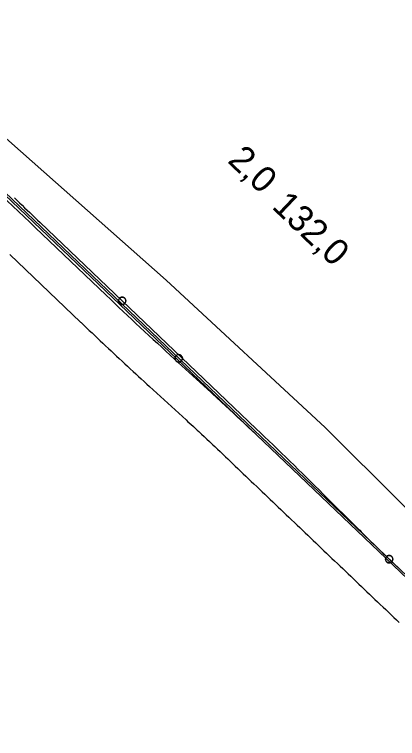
# Model space of a CAD drawing. Extents: x -670810 to -649614, y -1131928 to -1115069.
# Drawn here: x -666009 to -664978, y -1126558 to -1124610 of the extents above; entities that cross this region are included whole.
import ezdxf

# ---------------------------------------------------------------- set-up
doc = ezdxf.new("R2010")
doc.units = 0
for name, color, linetype in [('hranice_VRT_ZUR_Vysocina', 7, 'Continuous'), ('Situace - Osa koleje 2D', 7, 'Continuous'), ('Staničení - hlavní staničení + kolečka 1k', 7, 'Continuous')]:
    doc.layers.add(name, color=color, linetype=linetype)

# ---------------------------------------------------------------- blocks, each defined once
blk = doc.blocks.new('Sit10Kruh_109')
at = {"layer": 'Staničení - hlavní staničení + kolečka 1k'}
blk.add_lwpolyline([(10, 0), (9.98026, 0.6279), (9.92114, 1.25334), (9.82288, 1.87382), (9.68584, 2.4869), (9.51056, 3.09016), (9.29776, 3.68124), (9.04828, 4.2578), (8.76306, 4.81754), (8.44328, 5.35826), (8.09016, 5.87786), (7.70514, 6.37424), (7.28968, 6.84548), (6.84548, 7.28968), (6.37424, 7.70514), (5.87786, 8.09016), (5.35826, 8.44328), (4.81754, 8.76306), (4.2578, 9.04828), (3.68124, 9.29776), (3.09016, 9.51056), (2.4869, 9.68584), (1.87382, 9.82288), (1.25334, 9.92114), (0.6279, 9.98026), (0, 10), (-0.6279, 9.98026), (-1.25334, 9.92114), (-1.87382, 9.82288), (-2.4869, 9.68584), (-3.09016, 9.51056), (-3.68124, 9.29776), (-4.2578, 9.04828), (-4.81754, 8.76306), (-5.35826, 8.44328), (-5.87786, 8.09016), (-6.37424, 7.70514), (-6.84548, 7.28968), (-7.28968, 6.84548), (-7.70514, 6.37424), (-8.09016, 5.87786), (-8.44328, 5.35826), (-8.76306, 4.81754), (-9.04828, 4.2578), (-9.29776, 3.68124), (-9.51056, 3.09016), (-9.68584, 2.4869), (-9.82288, 1.87382), (-9.92114, 1.25334), (-9.98026, 0.6279), (-10, 0), (-9.98026, -0.6279), (-9.92114, -1.25334), (-9.82288, -1.87382), (-9.68584, -2.4869), (-9.51056, -3.09016), (-9.29776, -3.68124), (-9.04828, -4.2578), (-8.76306, -4.81754), (-8.44328, -5.35826), (-8.09016, -5.87786), (-7.70514, -6.37424), (-7.28968, -6.84548), (-6.84548, -7.28968), (-6.37424, -7.70514), (-5.87786, -8.09016), (-5.35826, -8.44328), (-4.81754, -8.76306), (-4.2578, -9.04828), (-3.68124, -9.29776), (-3.09016, -9.51056), (-2.4869, -9.68584), (-1.87382, -9.82288), (-1.25334, -9.92114), (-0.6279, -9.98026), (0, -10), (0.6279, -9.98026), (1.25334, -9.92114), (1.87382, -9.82288), (2.4869, -9.68584), (3.09016, -9.51056), (3.68124, -9.29776), (4.2578, -9.04828), (4.81754, -8.76306), (5.35826, -8.44328), (5.87786, -8.09016), (6.37424, -7.70514), (6.84548, -7.28968), (7.28968, -6.84548), (7.70514, -6.37424), (8.09016, -5.87786), (8.44328, -5.35826), (8.76306, -4.81754), (9.04828, -4.2578), (9.29776, -3.68124), (9.51056, -3.09016), (9.68584, -2.4869), (9.82288, -1.87382), (9.92114, -1.25334)], close=True, dxfattribs=at)
blk.add_circle((0, 0), 10, dxfattribs=at)
blk = doc.blocks.new('Sit10Kruh_185')
at = {"layer": 'Staničení - hlavní staničení + kolečka 1k'}
blk.add_lwpolyline([(10, 0), (10, 0.6), (9.9, 1.3), (9.8, 1.9), (9.7, 2.5), (9.5, 3.1), (9.3, 3.7), (9, 4.3), (8.8, 4.8), (8.4, 5.4), (8.1, 5.9), (7.7, 6.4), (7.3, 6.8), (6.8, 7.3), (6.4, 7.7), (5.9, 8.1), (5.4, 8.4), (4.8, 8.8), (4.3, 9), (3.7, 9.3), (3.1, 9.5), (2.5, 9.7), (1.9, 9.8), (1.3, 9.9), (0.6, 10), (0, 10), (-0.6, 10), (-1.3, 9.9), (-1.9, 9.8), (-2.5, 9.7), (-3.1, 9.5), (-3.7, 9.3), (-4.3, 9), (-4.8, 8.8), (-5.4, 8.4), (-5.9, 8.1), (-6.4, 7.7), (-6.8, 7.3), (-7.3, 6.8), (-7.7, 6.4), (-8.1, 5.9), (-8.4, 5.4), (-8.8, 4.8), (-9, 4.3), (-9.3, 3.7), (-9.5, 3.1), (-9.7, 2.5), (-9.8, 1.9), (-9.9, 1.3), (-10, 0.6), (-10, 0), (-10, -0.6), (-9.9, -1.3), (-9.8, -1.9), (-9.7, -2.5), (-9.5, -3.1), (-9.3, -3.7), (-9, -4.3), (-8.8, -4.8), (-8.4, -5.4), (-8.1, -5.9), (-7.7, -6.4), (-7.3, -6.8), (-6.8, -7.3), (-6.4, -7.7), (-5.9, -8.1), (-5.4, -8.4), (-4.8, -8.8), (-4.3, -9), (-3.7, -9.3), (-3.1, -9.5), (-2.5, -9.7), (-1.9, -9.8), (-1.3, -9.9), (-0.6, -10), (0, -10), (0.6, -10), (1.3, -9.9), (1.9, -9.8), (2.5, -9.7), (3.1, -9.5), (3.7, -9.3), (4.3, -9), (4.8, -8.8), (5.4, -8.4), (5.9, -8.1), (6.4, -7.7), (6.8, -7.3), (7.3, -6.8), (7.7, -6.4), (8.1, -5.9), (8.4, -5.4), (8.8, -4.8), (9, -4.3), (9.3, -3.7), (9.5, -3.1), (9.7, -2.5), (9.8, -1.9), (9.9, -1.3)], close=True, dxfattribs=at)
blk.add_circle((0, 0), 10, dxfattribs=at)
blk = doc.blocks.new('Sit10Kruh_186')
at = {"layer": 'Staničení - hlavní staničení + kolečka 1k'}
blk.add_lwpolyline([(10, 0), (10, 0.6), (9.9, 1.3), (9.8, 1.9), (9.7, 2.5), (9.5, 3.1), (9.3, 3.7), (9, 4.3), (8.8, 4.8), (8.4, 5.4), (8.1, 5.9), (7.7, 6.4), (7.3, 6.8), (6.8, 7.3), (6.4, 7.7), (5.9, 8.1), (5.4, 8.4), (4.8, 8.8), (4.3, 9), (3.7, 9.3), (3.1, 9.5), (2.5, 9.7), (1.9, 9.8), (1.3, 9.9), (0.6, 10), (0, 10), (-0.6, 10), (-1.3, 9.9), (-1.9, 9.8), (-2.5, 9.7), (-3.1, 9.5), (-3.7, 9.3), (-4.3, 9), (-4.8, 8.8), (-5.4, 8.4), (-5.9, 8.1), (-6.4, 7.7), (-6.8, 7.3), (-7.3, 6.8), (-7.7, 6.4), (-8.1, 5.9), (-8.4, 5.4), (-8.8, 4.8), (-9, 4.3), (-9.3, 3.7), (-9.5, 3.1), (-9.7, 2.5), (-9.8, 1.9), (-9.9, 1.3), (-10, 0.6), (-10, 0), (-10, -0.6), (-9.9, -1.3), (-9.8, -1.9), (-9.7, -2.5), (-9.5, -3.1), (-9.3, -3.7), (-9, -4.3), (-8.8, -4.8), (-8.4, -5.4), (-8.1, -5.9), (-7.7, -6.4), (-7.3, -6.8), (-6.8, -7.3), (-6.4, -7.7), (-5.9, -8.1), (-5.4, -8.4), (-4.8, -8.8), (-4.3, -9), (-3.7, -9.3), (-3.1, -9.5), (-2.5, -9.7), (-1.9, -9.8), (-1.3, -9.9), (-0.6, -10), (0, -10), (0.6, -10), (1.3, -9.9), (1.9, -9.8), (2.5, -9.7), (3.1, -9.5), (3.7, -9.3), (4.3, -9), (4.8, -8.8), (5.4, -8.4), (5.9, -8.1), (6.4, -7.7), (6.8, -7.3), (7.3, -6.8), (7.7, -6.4), (8.1, -5.9), (8.4, -5.4), (8.8, -4.8), (9, -4.3), (9.3, -3.7), (9.5, -3.1), (9.7, -2.5), (9.8, -1.9), (9.9, -1.3)], close=True, dxfattribs=at)
blk.add_circle((0, 0), 10, dxfattribs=at)

msp = doc.modelspace()

# ---------------------------------------------------------------- linework, layer by layer
at = {"layer": 'hranice_VRT_ZUR_Vysocina'}
for points in [[(-665993.2, -1124977.6), (-666490.4, -1124537.4), (-666642.8, -1124402.4)], [(-665993.2, -1124977.6), (-665600.9, -1125324.5), (-665173.4, -1125720.6), (-664760.4, -1126131.5), (-664347, -1126557.9)], [(-666022.4, -1125255.4), (-665831.4, -1125437.6), (-665829.9, -1125438.9), (-665822.6, -1125445.9), (-665815.3, -1125452.8), (-665808, -1125459.8), (-665800.7, -1125466.7), (-665793.4, -1125473.6), (-665786, -1125480.6), (-665778.7, -1125487.5), (-665771.4, -1125494.4), (-665764, -1125501.3), (-665756.7, -1125508.2), (-665749.3, -1125515.1), (-665741.9, -1125522), (-665734.6, -1125528.9), (-665727.2, -1125535.7), (-665719.8, -1125542.6), (-665712.4, -1125549.5), (-665705, -1125556.3), (-665697.6, -1125563.2), (-665690.2, -1125570), (-665682.8, -1125576.9), (-665675.4, -1125583.7), (-665668, -1125590.5), (-665660.6, -1125597.3), (-665653.1, -1125604.1), (-665645.8, -1125610.8), (-665547.5, -1125700.7), (-665542.4, -1125705.4), (-665535.1, -1125712), (-665527.9, -1125718.7), (-665520.6, -1125725.4), (-665517.2, -1125728.6), (-665513.4, -1125732.1), (-665506.2, -1125738.8), (-665499, -1125745.5), (-665491.8, -1125752.2), (-665484.6, -1125758.9), (-665477.4, -1125765.7), (-665475.4, -1125767.5), (-665470.2, -1125772.4), (-665463.1, -1125779.2), (-665455.9, -1125786), (-665448.7, -1125792.8), (-665441.6, -1125799.6), (-665435.2, -1125805.6)], [(-665435.2, -1125805.6), (-665429.7, -1125810.9), (-665422.5, -1125817.8), (-665415.2, -1125824.7), (-665408, -1125831.6), (-665400.8, -1125838.5), (-665393.5, -1125845.4), (-665386.3, -1125852.3), (-665379.1, -1125859.2), (-665371.8, -1125866.1), (-665364.6, -1125873), (-665357.3, -1125879.9), (-665350.1, -1125886.8), (-665342.9, -1125893.7), (-665335.6, -1125900.6), (-665328.4, -1125907.5), (-665321.2, -1125914.4), (-665313.9, -1125921.3), (-665306.7, -1125928.2), (-665299.5, -1125935.1), (-665292.2, -1125942), (-665285, -1125948.9), (-665277.7, -1125955.8), (-665270.5, -1125962.7), (-665263.3, -1125969.6), (-665256, -1125976.5), (-665248.8, -1125983.5), (-665241.6, -1125990.4), (-665234.3, -1125997.3), (-665227.1, -1126004.2), (-665219.8, -1126011.1), (-665212.6, -1126018), (-665205.4, -1126024.9), (-665198.1, -1126031.8), (-665190.9, -1126038.7), (-665183.7, -1126045.6), (-665176.4, -1126052.5), (-665169.2, -1126059.4), (-665162, -1126066.3), (-665154.7, -1126073.2), (-665147.5, -1126080.1), (-665140.2, -1126087), (-665133, -1126093.9), (-665125.8, -1126100.8), (-665118.5, -1126107.7), (-665111.3, -1126114.6), (-665104.1, -1126121.5), (-665096.8, -1126128.4), (-665089.6, -1126135.3), (-665082.3, -1126142.2), (-665075.1, -1126149.1), (-665067.9, -1126156), (-665060.6, -1126162.9), (-665053.4, -1126169.8), (-665046.2, -1126176.7), (-665038.9, -1126183.6), (-665031.7, -1126190.5), (-665024.5, -1126197.4), (-665017.2, -1126204.3), (-665010, -1126211.2), (-665002.7, -1126218.1), (-664995.5, -1126225), (-664988.3, -1126231.9), (-664981, -1126238.8), (-664973.8, -1126245.7)]]:
    msp.add_lwpolyline(points, dxfattribs=at)
at = {"layer": 'Situace - Osa koleje 2D'}
for p, q in [((-667875.9, -1123340), (-664682.6, -1126385.2)), ((-667872.7, -1123336.5), (-664677.5, -1126383.5)), ((-665953.4, -1125183), (-665762.4, -1125365.2)), ((-665940.5, -1125169.4), (-665358.6, -1125724.4)), ((-665578.3, -1125537), (-665480, -1125626.9)), ((-665372.3, -1125727.5), (-665366.2, -1125733.3)), ((-665178.2, -1125900), (-665083.8, -1125994))]:
    msp.add_line(p, q, dxfattribs=at)
msp.add_lwpolyline([(-666009.5, -1125102.6), (-666002.7, -1125109.4), (-665995.8, -1125116.2), (-665989, -1125122.9), (-665982.1, -1125129.6), (-665975.2, -1125136.3), (-665968.3, -1125142.9), (-665961.3, -1125149.6), (-665954.4, -1125156.2), (-665947.5, -1125162.8), (-665940.5, -1125169.4)], dxfattribs=at)
for centre, radius, start, end in [((-674235, -1133867.2), 12000, 46.35959, 47.95109), ((-657480.8, -1116681), 12000, 226.35959, 227.56174), ((-670969.3, -1131630.4), 8134.7, 47.26822, 47.56174), ((-669588.6, -1130135.8), 6100, 46.72286, 47.26822), ((-670559.3, -1131166.8), 7516, 46.35959, 46.72286), ((-673640.2, -1134408.6), 12000, 45.15743, 46.35959), ((-659347.5, -1120226.1), 8134.7, 225.15743, 225.45096), ((-660774.9, -1121676.1), 6100, 225.45096, 225.99631), ((-659791.1, -1120657.6), 7516, 225.99631, 226.35959)]:
    msp.add_arc(centre, radius, start, end, dxfattribs=at)

# ---------------------------------------------------------------- block references
at = {"layer": 'Staničení - hlavní staničení + kolečka 1k'}
for name, p, rotation in [('Sit10Kruh_185', (-665719.5, -1125380.2), -43.640410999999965), ('Sit10Kruh_109', (-665567.3, -1125535), -43.640410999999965), ('Sit10Kruh_186', (-665000.7, -1126075.3), -43.877967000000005)]:
    msp.add_blockref(name, p, dxfattribs=dict(at, rotation=rotation))

# ---------------------------------------------------------------- texts
for s, p in [('2,0', (-665438.4, -1125005.7)), ('132,0', (-665319, -1125129.3))]:
    msp.add_text(s, height=70, rotation=316.3596, dxfattribs=at).set_placement(p)

doc.saveas('drawing.dxf')
